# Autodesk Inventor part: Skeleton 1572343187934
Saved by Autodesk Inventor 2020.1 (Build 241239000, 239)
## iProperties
Created: 2019-10
Part Number: Skeleton 1572343187934
Material: Generic
Document SubType Name: Modeling
Designer: Synergysoft Dell02
Density: 1 g/cm^3
Appearance: Default
_SkeletonDoc: Frame Skeleton File
_Version: 15.0.0
Author: Synergysoft Dell02
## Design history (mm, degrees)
sketch "Reference Skeleton"
